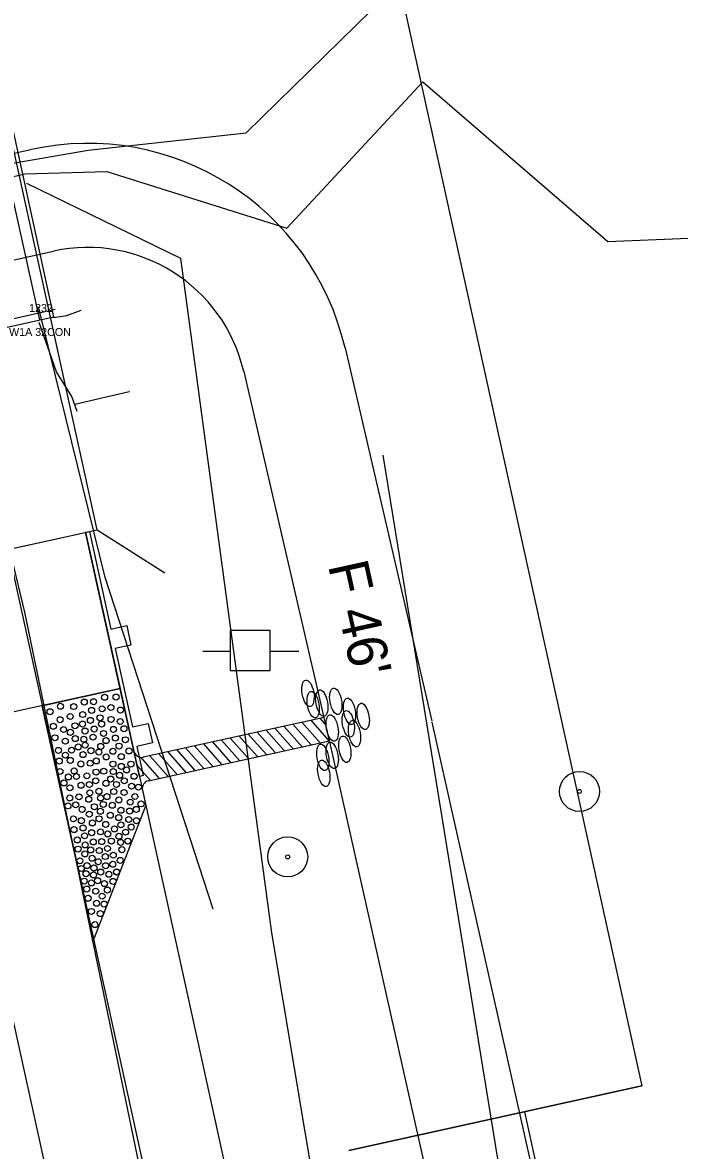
# Model space of a CAD drawing. Extents: x 2519952 to 2531965, y 848341 to 887632.
# Drawn here: x 2530998 to 2531080.1, y 852373.9 to 852514.8 of the extents above; entities that cross this region are included whole.
import ezdxf

# ---------------------------------------------------------------- set-up
doc = ezdxf.new("R2010")
doc.units = 0
for name, color, linetype in [('RD_EV_JW', 7, 'Continuous'), ('RD_EX_BldgApp', 7, 'Continuous'), ('RD_EX_BldgApp_txCode', 7, 'Continuous'), ('RD_EX_Bridge', 7, 'Continuous'), ('RD_EX_Conc', 7, 'Continuous'), ('RD_EX_DR_Pipe', 7, 'Continuous'), ('RD_EX_DV_Prop', 7, 'Continuous'), ('RD_EX_DV_PropPin', 7, 'Continuous'), ('RD_EX_GuardRail', 7, 'Continuous'), ('RD_EX_H2O', 7, 'Continuous'), ('RD_EX_Misc', 7, 'Continuous'), ('RD_EX_Road', 7, 'Continuous'), ('RD_EX_RW', 7, 'Continuous'), ('RD_EX_UT', 7, 'Continuous'), ('RD_EX_VEG', 7, 'Continuous'), ('RD_HC_Cl', 7, 'Continuous'), ('RD_PD_Bridge', 7, 'Continuous'), ('RD_PD_CstnLmt', 7, 'Continuous'), ('RD_PD_DR_ErosCtrl', 7, 'Continuous'), ('RD_PD_Final_TrvlWay', 7, 'Continuous'), ('RD_PD_GR', 7, 'Continuous'), ('RD_PD_PaveShd', 7, 'Continuous'), ('RD_PD_RW', 7, 'Continuous'), ('RD_PD_TX_CstnLmt', 7, 'Continuous'), ('RD_SMD_Locator', 7, 'Continuous')]:
    doc.layers.add(name, color=color, linetype=linetype)

# ---------------------------------------------------------------- blocks, each defined once
blk = doc.blocks.new('TBC1')
at = {"layer": 'RD_PD_GR'}
blk.add_lwpolyline([(12.5, 2.5), (15, 2.5), (15, 0.49), (25, 0.49), (25, 2.5), (27.5, 2.5), (27.5, 0.49), (31.25, 0.49), (31.25, 0), (0, 0), (0, 0.49), (12.5, 0.49)], close=True, dxfattribs=at)

msp = doc.modelspace()

# ---------------------------------------------------------------- linework, layer by layer
at = {"layer": 'RD_EV_JW'}
msp.add_lwpolyline([(2531125.63, 851940.25), (2531091.18, 852099.75), (2531068.77, 852205.2), (2531044.69, 852308.54), (2531029.19, 852401.02), (2531017.83, 852485.31), (2530998.59, 852494.65)], dxfattribs=at)
at = {"layer": 'RD_EX_BldgApp'}
msp.add_lwpolyline([(2531000.2, 852477.61), (2530992.08, 852514.14), (2530984.07, 852551.68)], dxfattribs=at)
at = {"layer": 'RD_EX_Bridge'}
for points in [[(2530955.67, 852467.77), (2531001.96, 852478), (2530985.83, 852552.07), (2530938.91, 852541.61), (2530955.67, 852467.77)], [(2531001.91, 852477.9), (2531003.6, 852478.17), (2531005.36, 852478.83)]]:
    msp.add_lwpolyline(points, dxfattribs=at)
at = {"layer": 'RD_EX_Conc'}
msp.add_lwpolyline([(2531004.88, 852466.18), (2531004.22, 852468.06), (2531002.3, 852471.13), (2531000.13, 852477.28)], dxfattribs=at)
at = {"layer": 'RD_EX_DR_Pipe'}
msp.add_line((2531004.6, 852467.1), (2531011.39, 852468.67), dxfattribs=at)
at = {"layer": 'RD_EX_DV_Prop'}
for p, q in [((2531010.91, 852674.9), (2531075.43, 852381.91)), ((2531075.43, 852381.91), (2531038.81, 852373.85))]:
    msp.add_line(p, q, dxfattribs=at)
at = {"layer": 'RD_EX_DV_PropPin'}
for centre, radius in [((2531067.65, 852418.7), 2.5), ((2531067.65, 852418.7), 0.25), ((2531031.18, 852410.53), 2.5), ((2531031.18, 852410.53), 0.25)]:
    msp.add_circle(centre, radius, dxfattribs=at)
at = {"layer": 'RD_EX_GuardRail'}
msp.add_lwpolyline([(2531021.88, 852403.99), (2531008.37, 852445.44), (2531000.04, 852479.26)], dxfattribs=at)
at = {"layer": 'RD_EX_H2O'}
for points in [[(2530763.58, 852156.52), (2530778.88, 852247.16), (2530808.35, 852291.93), (2530804.53, 852318.45), (2530767.34, 852345.6), (2530781.71, 852364.29), (2530813.82, 852387.86), (2530859.93, 852427.22), (2530925.48, 852467.07), (2530950.14, 852489.17), (2531006.23, 852498.83), (2531006.23, 852498.83), (2531026, 852501), (2531071.02, 852545.11)], [(2531008.59, 852496.17), (2531031.07, 852489.09), (2531048.09, 852507.37), (2531071.2, 852487.42), (2531108.56, 852488.95), (2531147.12, 852499.68), (2531158.94, 852473.54)], [(2530973.5, 852331.3), (2530944.44, 852441.73), (2530937.03, 852452.89), (2530951.23, 852484.72), (2530998.33, 852495.88), (2531008.59, 852496.17)]]:
    msp.add_lwpolyline(points, dxfattribs=at)
at = {"layer": 'RD_EX_Misc'}
msp.add_line((2530955.19, 852468.48), (2531002.11, 852478.96), dxfattribs=at)
at = {"layer": 'RD_EX_Road'}
for p, q in [((2530998.34, 852441.09), (2530990.14, 852475.05)), ((2531018.73, 852342.63), (2530998.34, 852441.09))]:
    msp.add_line(p, q, dxfattribs=at)
at = {"layer": 'RD_EX_RW'}
for p in [(2531010.92, 852674.89), (2531038.81, 852373.85)]:
    msp.add_line(p, (2531075.43, 852381.91), dxfattribs=at)
at = {"layer": 'RD_EX_UT'}
for p, q in [((2531028.99, 852438.8), (2531023.99, 852438.8)), ((2531023.99, 852438.8), (2531023.99, 852433.8)), ((2531028.99, 852433.8), (2531028.99, 852438.8)), ((2531020.56, 852436.23), (2531024.03, 852436.23)), ((2531028.92, 852436.23), (2531032.56, 852436.23)), ((2531023.99, 852433.8), (2531028.99, 852433.8))]:
    msp.add_line(p, q, dxfattribs=at)
at = {"layer": 'RD_EX_VEG'}
msp.add_lwpolyline([(2531179.51, 851966.14), (2531146.93, 851949.23), (2531105.69, 852161.62), (2531061.1, 852350.33), (2531043.12, 852460.73)], dxfattribs=at)
at = {"layer": 'RD_HC_Cl'}
msp.add_line((2530821.93, 853184.38), (2531378.52, 850656.73), dxfattribs=at)
at = {"layer": 'RD_PD_Bridge'}
for p, q in [((2530961.49, 852441.3), (2531007.39, 852451.41)), ((2531005.93, 852451.09), (2531010.23, 852431.55)), ((2531007.39, 852451.41), (2531015.82, 852446.02)), ((2531010.23, 852431.55), (2530967.26, 852422.09))]:
    msp.add_line(p, q, dxfattribs=at)
for points in [[(2531007.39, 852451.41), (2530979.44, 852578.37)], [(2530961.49, 852441.3), (2531007.39, 852451.41)]]:
    msp.add_lwpolyline(points, dxfattribs=at)
at = {"layer": 'RD_PD_CstnLmt'}
for p, q in [((2531025.68, 852471.19), (2531036.51, 852424.54)), ((2531036.51, 852424.54), (2531058.37, 852326.96))]:
    msp.add_line(p, q, dxfattribs=at)
msp.add_lwpolyline([(2530951.36, 852475.07), (2531001.9, 852486.2)], dxfattribs=at)
msp.add_arc((2531006.2, 852466.67), 20, 13.0724, 102.4185, dxfattribs=at)
at = {"layer": 'RD_PD_DR_ErosCtrl'}
for p, q in [((2531038.35, 852474.13), (2531049.18, 852427.48)), ((2531049.2, 852427.38), (2531071.06, 852329.8))]:
    msp.add_line(p, q, dxfattribs=at)
msp.add_lwpolyline([(2530948.56, 852487.77), (2530999.1, 852498.9)], dxfattribs=at)
msp.add_arc((2531006.2, 852466.67), 33, 13.0724, 102.4185, dxfattribs=at)
at = {"layer": 'RD_PD_Final_TrvlWay'}
msp.add_line((2530922.51, 852783.42), (2531196.7, 851538.25), dxfattribs=at)
at = {"layer": 'RD_PD_GR'}
msp.add_line((2531012.65, 852420.57), (2531171.25, 851700.32), dxfattribs=at)
at = {"layer": 'RD_PD_PaveShd'}
for p, q in [((2531000.46, 852429.4), (2531010.23, 852431.55)), ((2531010.23, 852431.55), (2531012.16, 852422.77)), ((2531000.46, 852429.4), (2531006.91, 852400.11)), ((2531035.72, 852427.96), (2531013.14, 852422.98)), ((2531035.18, 852427.85), (2531035.95, 852426.97)), ((2531036.4, 852425.04), (2531035.72, 852427.96)), ((2531029.59, 852426.61), (2531031.87, 852424.04)), ((2531029.59, 852426.61), (2531031.87, 852424.04)), ((2531030.71, 852426.86), (2531032.98, 852424.29)), ((2531030.71, 852426.86), (2531032.98, 852424.29)), ((2531031.83, 852427.11), (2531034.1, 852424.54)), ((2531031.83, 852427.11), (2531034.1, 852424.54)), ((2531032.94, 852427.35), (2531035.22, 852424.78)), ((2531032.94, 852427.35), (2531035.22, 852424.78)), ((2531034.06, 852427.6), (2531036.34, 852425.03)), ((2531034.06, 852427.6), (2531036.34, 852425.03)), ((2531013.79, 852420.05), (2531036.4, 852425.04)), ((2531022.89, 852425.13), (2531025.17, 852422.56)), ((2531022.89, 852425.13), (2531025.17, 852422.56)), ((2531024.01, 852425.38), (2531026.28, 852422.81)), ((2531024.01, 852425.38), (2531026.28, 852422.81)), ((2531025.13, 852425.63), (2531027.4, 852423.06)), ((2531025.13, 852425.63), (2531027.4, 852423.06)), ((2531026.24, 852425.87), (2531028.52, 852423.3)), ((2531026.24, 852425.87), (2531028.52, 852423.3)), ((2531027.36, 852426.12), (2531029.35, 852423.87)), ((2531027.36, 852426.12), (2531029.63, 852423.55)), ((2531028.48, 852426.37), (2531030.75, 852423.8)), ((2531028.48, 852426.37), (2531030.75, 852423.8)), ((2531016.19, 852423.65), (2531018.46, 852421.08)), ((2531016.19, 852423.65), (2531018.46, 852421.08)), ((2531017.31, 852423.9), (2531019.58, 852421.33)), ((2531018.42, 852424.15), (2531020.7, 852421.58)), ((2531018.42, 852424.15), (2531020.7, 852421.58)), ((2531019.54, 852424.39), (2531021.81, 852421.82)), ((2531019.54, 852424.39), (2531021.81, 852421.82)), ((2531020.66, 852424.64), (2531022.93, 852422.07)), ((2531020.66, 852424.64), (2531022.93, 852422.07)), ((2531021.77, 852424.89), (2531024.05, 852422.32)), ((2531021.77, 852424.89), (2531024.05, 852422.32)), ((2531012.16, 852422.77), (2531012.81, 852419.84)), ((2531012.79, 852422.97), (2531015.11, 852420.34)), ((2531013.95, 852423.16), (2531016.23, 852420.59)), ((2531013.95, 852423.16), (2531016.23, 852420.59)), ((2531015.07, 852423.41), (2531017.35, 852420.84)), ((2531015.07, 852423.41), (2531017.35, 852420.84)), ((2531012.34, 852421.97), (2531013.99, 852420.1)), ((2531012.81, 852419.84), (2531013.46, 852416.91)), ((2531006.91, 852400.11), (2531013.46, 852416.91))]:
    msp.add_line(p, q, dxfattribs=at)
for centre in [(2531008.3, 852430.47), (2531008.3, 852430.47), (2531009.73, 852430.5), (2531009.73, 852430.5), (2531009.73, 852430.5), (2531002.78, 852429.35), (2531002.78, 852429.35), (2531004.44, 852429.31), (2531004.44, 852429.31), (2531005.76, 852429.87), (2531005.76, 852429.87), (2531006.92, 852429.91), (2531006.92, 852429.91), (2531007.99, 852429.03), (2531007.99, 852429.03), (2531009.09, 852429.19), (2531009.09, 852429.19), (2531010.28, 852428.87), (2531010.28, 852428.87), (2531001.48, 852428.67), (2531001.48, 852428.67), (2531002.74, 852427.67), (2531002.74, 852427.67), (2531004, 852428.07), (2531004, 852428.07), (2531005.56, 852428.31), (2531005.56, 852428.31), (2531006.52, 852427.58), (2531006.52, 852427.58), (2531006.68, 852428.83), (2531006.68, 852428.83), (2531007.73, 852427.91), (2531007.73, 852427.91), (2531009.11, 852427.7), (2531009.11, 852427.7), (2531001.9, 852426.85), (2531001.9, 852426.85), (2531003.17, 852426.44), (2531003.17, 852426.44), (2531004.02, 852426.09), (2531004.02, 852426.09), (2531004.6, 852426.91), (2531004.6, 852426.91), (2531005.54, 852427.12), (2531005.54, 852427.12), (2531005.85, 852426.25), (2531005.85, 852426.25), (2531007, 852426.5), (2531007, 852426.5), (2531007.93, 852427.13), (2531007.93, 852427.13), (2531009.41, 852426.46), (2531009.41, 852426.46), (2531010.25, 852427.44), (2531010.25, 852427.44), (2531010.72, 852426.54), (2531010.72, 852426.54), (2531002.09, 852425.41), (2531002.09, 852425.41), (2531003.39, 852424.99), (2531003.39, 852424.99), (2531004.64, 852425.31), (2531004.64, 852425.31), (2531005.7, 852425.23), (2531006.85, 852425.49), (2531006.85, 852425.49), (2531008.17, 852425.95), (2531008.17, 852425.95), (2531008.48, 852425.06), (2531008.48, 852425.06), (2531009.65, 852425.38), (2531009.65, 852425.38), (2531010.9, 852425.16), (2531010.9, 852425.16), (2531002.53, 852423.84), (2531002.53, 852423.84), (2531003.4, 852423.24), (2531003.4, 852423.24), (2531004.17, 852423.86), (2531004.17, 852423.86), (2531005, 852424.26), (2531005, 852424.26), (2531005.6, 852423.3), (2531005.6, 852423.3), (2531005.87, 852424.49), (2531005.87, 852424.49), (2531006.59, 852423.79), (2531006.59, 852423.79), (2531007.58, 852423.63), (2531007.58, 852423.63), (2531007.82, 852424.34), (2531007.82, 852424.34), (2531009.33, 852423.72), (2531009.33, 852423.72), (2531010.1, 852424.37), (2531010.1, 852424.37), (2531011.35, 852423.76), (2531011.35, 852423.76), (2531002.63, 852422.5), (2531002.63, 852422.5), (2531004.01, 852422.58), (2531004.01, 852422.58), (2531005.33, 852422.14), (2531005.33, 852422.14), (2531006.49, 852422.23), (2531006.49, 852422.23), (2531007.26, 852422.52), (2531007.26, 852422.52), (2531008.5, 852423.01), (2531008.5, 852423.01), (2531009.34, 852422.12), (2531009.34, 852422.12), (2531010.38, 852423.06), (2531010.38, 852423.06), (2531010.38, 852421.83), (2531010.38, 852421.83), (2531011.59, 852422.12), (2531011.59, 852422.12), (2531002.72, 852421.2), (2531002.72, 852421.2), (2531003.77, 852420.52), (2531003.77, 852420.52), (2531004.49, 852421.26), (2531004.49, 852421.26), (2531004.78, 852420.57), (2531004.78, 852420.57), (2531006.08, 852420.66), (2531006.08, 852420.66), (2531007.23, 852421.12), (2531007.23, 852421.12), (2531008.19, 852421.23), (2531008.19, 852421.23), (2531009.39, 852421.19), (2531009.39, 852421.19), (2531010.18, 852420.72), (2531010.18, 852420.72), (2531011.04, 852421.39), (2531011.04, 852421.39), (2531011.98, 852420.6), (2531011.98, 852420.6), (2531003.22, 852419.76), (2531003.97, 852419.16), (2531003.97, 852419.16), (2531005.36, 852419.47), (2531005.36, 852419.47), (2531006.4, 852419.57), (2531006.4, 852419.57), (2531007.19, 852420.03), (2531007.19, 852420.03), (2531008.47, 852419.73), (2531008.47, 852419.73), (2531009.06, 852420.25), (2531009.06, 852420.25), (2531009.78, 852419.58), (2531009.78, 852419.58), (2531010.76, 852420.03), (2531010.76, 852420.03), (2531011.68, 852419.36), (2531011.68, 852419.36), (2531012.53, 852419.24), (2531012.53, 852419.24), (2531003.95, 852417.89), (2531003.95, 852417.89), (2531005.1, 852418.03), (2531005.1, 852418.03), (2531006.32, 852417.73), (2531006.32, 852417.73), (2531006.46, 852418.53), (2531006.46, 852418.53), (2531007.59, 852418.72), (2531007.59, 852418.72), (2531007.79, 852417.89), (2531007.79, 852417.89), (2531008.59, 852418.06), (2531008.59, 852418.06), (2531009.44, 852418.69), (2531009.44, 852418.69), (2531010.08, 852417.64), (2531010.08, 852417.64), (2531010.73, 852418.57), (2531010.73, 852418.57), (2531012.08, 852418.07), (2531012.08, 852418.07), (2531003.72, 852416.9), (2531003.72, 852416.9), (2531004.69, 852417.03), (2531004.69, 852417.03), (2531005.49, 852416.46), (2531005.49, 852416.46), (2531007.02, 852416.79), (2531007.02, 852416.79), (2531007.77, 852416.23), (2531007.77, 852416.23), (2531008.13, 852417.08), (2531008.13, 852417.08), (2531009.26, 852416.98), (2531009.26, 852416.98), (2531010.34, 852416.35), (2531010.34, 852416.35), (2531011.43, 852416.26), (2531011.43, 852416.26), (2531011.5, 852417.37), (2531011.5, 852417.37), (2531012.26, 852416.46), (2531012.26, 852416.46), (2531012.86, 852417.15), (2531012.86, 852417.15), (2531012.86, 852417.15), (2531004.41, 852415.28), (2531004.41, 852415.28), (2531005.4, 852415.06), (2531005.4, 852415.06), (2531006.38, 852415.86), (2531006.38, 852415.86), (2531006.77, 852414.77), (2531006.77, 852414.77), (2531007.6, 852415.29), (2531007.6, 852415.29), (2531009.01, 852415.73), (2531009.01, 852415.73), (2531010.06, 852415.44), (2531010.06, 852415.44), (2531011.31, 852415.2), (2531011.31, 852415.2), (2531012.28, 852415.05), (2531012.28, 852415.05), (2531004.47, 852413.93), (2531004.47, 852413.93), (2531005.6, 852414.14), (2531005.6, 852414.14), (2531006.68, 852413.55), (2531006.68, 852413.55), (2531007.79, 852413.65), (2531007.79, 852413.65), (2531008.44, 852414.59), (2531008.44, 852414.59), (2531008.7, 852413.39), (2531008.7, 852413.39), (2531009.53, 852414.02), (2531009.53, 852414.02), (2531010.34, 852414.53), (2531010.34, 852414.53), (2531010.93, 852413.62), (2531010.93, 852413.62), (2531011.62, 852414.25), (2531011.62, 852414.25), (2531004.89, 852412.64), (2531004.89, 852412.64), (2531005.79, 852413.16), (2531005.79, 852413.16), (2531005.87, 852412.02), (2531005.87, 852412.02), (2531006.88, 852412.39), (2531006.88, 852412.39), (2531007.94, 852412.44), (2531007.94, 852412.44), (2531009.15, 852412.5), (2531009.15, 852412.5), (2531010.09, 852413.11), (2531010.09, 852413.11), (2531010.29, 852412.34), (2531010.29, 852412.34), (2531011.2, 852412.5), (2531011.21, 852412.5), (2531004.98, 852411.5), (2531004.98, 852411.5), (2531005.83, 852410.9), (2531005.83, 852410.9), (2531006.56, 852411.4), (2531006.56, 852411.4), (2531007.63, 852411.32), (2531007.63, 852411.32), (2531008.38, 852410.57), (2531008.38, 852410.57), (2531008.66, 852411.58), (2531008.66, 852411.58), (2531009.38, 852410.74), (2531009.38, 852410.74), (2531010.46, 852411.43), (2531010.46, 852411.43), (2531005.21, 852410.04), (2531005.21, 852410.04), (2531006.11, 852409.44), (2531006.11, 852409.44), (2531006.74, 852410.35), (2531006.74, 852410.35), (2531006.97, 852409.15), (2531006.97, 852409.15), (2531007.5, 852409.92), (2531007.5, 852409.92), (2531008.43, 852409.43), (2531008.43, 852409.43), (2531009.33, 852409.6), (2531009.33, 852409.6), (2531010.25, 852410.09), (2531010.25, 852410.09), (2531005.39, 852409.08), (2531005.39, 852409.08), (2531005.98, 852408.42), (2531005.98, 852408.42), (2531006.92, 852408.27), (2531006.92, 852408.27), (2531007.81, 852408.63), (2531007.81, 852408.63), (2531008.83, 852408.36), (2531008.83, 852408.36), (2531009.79, 852408.63), (2531009.8, 852408.66), (2531005.75, 852407.5), (2531005.75, 852407.5), (2531006.06, 852406.51), (2531006.06, 852406.51), (2531006.66, 852407.27), (2531006.66, 852407.27), (2531007.43, 852407.55), (2531007.43, 852407.55), (2531008.28, 852407.19), (2531008.28, 852407.19), (2531008.65, 852406.39), (2531009.35, 852407.47), (2531009.35, 852407.47), (2531006.24, 852405.36), (2531006.24, 852405.36), (2531007.19, 852406.25), (2531007.19, 852406.25), (2531007.99, 852405.62), (2531007.99, 852405.62), (2531006.65, 852403.71), (2531006.65, 852403.71), (2531007.29, 852404.73), (2531007.29, 852404.73), (2531008.24, 852404.64), (2531008.24, 852404.64), (2531007.76, 852403.44), (2531007.76, 852403.44), (2531007.08, 852402.07)]:
    msp.add_circle(centre, 0.375, dxfattribs=at)
for centre, start, end in [((2531012.93, 852423.96), 192.4185, 282.4481), ((2531014, 852419.07), 102.4481, 192.4185)]:
    msp.add_arc(centre, 1, start, end, dxfattribs=at)
for centre in [(2531033.72, 852430.97), (2531033.72, 852430.97), (2531034.37, 852429.54), (2531034.37, 852429.54), (2531035.44, 852429.74), (2531035.44, 852429.74), (2531037.19, 852429.97), (2531037.19, 852429.97), (2531038.91, 852428.72), (2531038.91, 852428.72), (2531040.62, 852428.08), (2531040.62, 852428.08), (2531036.75, 852426.63), (2531036.75, 852426.63), (2531038.76, 852427.15), (2531038.76, 852427.15), (2531039.53, 852425.93), (2531039.53, 852425.93), (2531038.32, 852423.98), (2531038.32, 852423.98), (2531035.57, 852422.96), (2531036.75, 852423.21), (2531036.75, 852423.21), (2531035.69, 852420.97)]:
    msp.add_ellipse(centre, major_axis=(0.29, -1.65), ratio=0.429445, dxfattribs=at)
at = {"layer": 'RD_PD_RW'}
msp.add_line((2531060.78, 852378.69), (2531168.31, 851890.39), dxfattribs=at)
at = {"layer": 'RD_SMD_Locator'}
for centre in [(2531048.09, 852507.37), (2531026, 852501), (2531006.23, 852498.83), (2531006.23, 852498.83), (2530998.33, 852495.88), (2531008.59, 852496.17), (2531008.59, 852496.17), (2530998.59, 852494.65), (2531031.07, 852489.09), (2531071.2, 852487.42), (2531017.83, 852485.31), (2531000.04, 852479.26), (2531002.11, 852478.96), (2531005.36, 852478.83), (2531000.13, 852477.28), (2531000.2, 852477.61), (2531001.91, 852477.9), (2531001.96, 852478), (2531003.6, 852478.17), (2531002.3, 852471.13), (2531004.22, 852468.06), (2531011.39, 852468.67), (2531004.6, 852467.1), (2531004.88, 852466.18), (2531043.12, 852460.73), (2531008.37, 852445.44), (2530998.34, 852441.09), (2531028.15, 852419.4), (2531021.88, 852403.99), (2531029.19, 852401.02)]:
    msp.add_circle(centre, 0.001, dxfattribs=at)

# ---------------------------------------------------------------- block references
at = {"layer": 'RD_PD_Bridge', "rotation": -77.58151740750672}
msp.add_blockref('TBC1', (2531005.93, 852451.09), dxfattribs=at)

# ---------------------------------------------------------------- texts
at = {"layer": 'RD_EX_BldgApp_txCode'}
for s, p in [('1232', (2530998.86, 852478.61)), ('W1A 32CON', (2530996.36, 852475.61))]:
    msp.add_text(s, height=1, dxfattribs=at).set_placement(p)
at = {"layer": 'RD_PD_TX_CstnLmt'}
msp.add_text("F 46'", height=5, rotation=282.4185, dxfattribs=at).set_placement((2531036.2, 852446.97))

doc.saveas('drawing.dxf')
